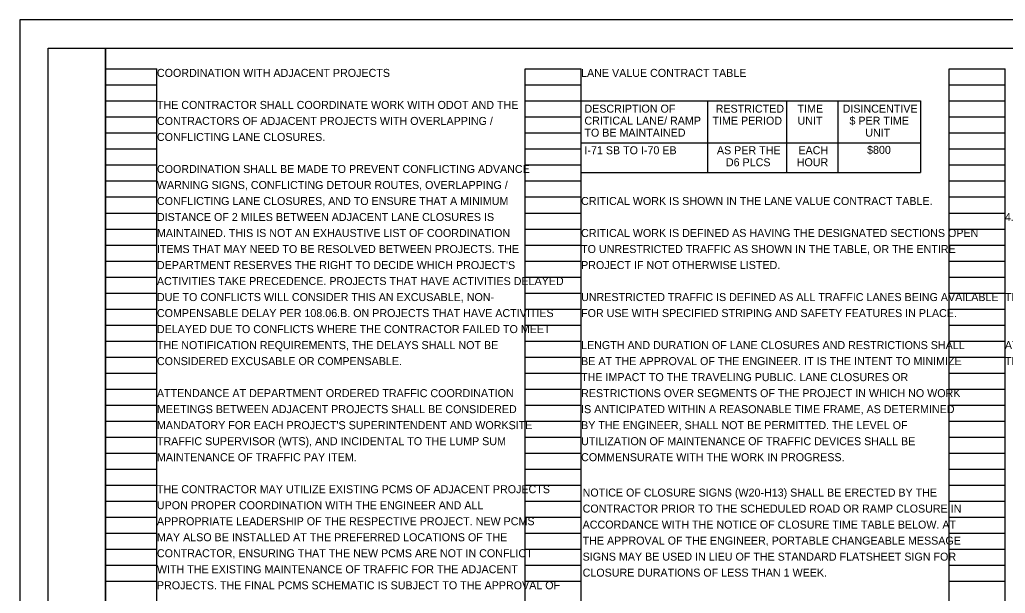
# Model space of a CAD drawing. Extents: x 0 to 34, y 0 to 22.
# Drawn here: x 0 to 17.24, y 11.97 to 22 of the extents above; entities that cross this region are included whole.
import ezdxf

# ---------------------------------------------------------------- set-up
doc = ezdxf.new("R2010")
doc.units = 0
for name, color, linetype in [('SH_Border', 7, 'Continuous'), ('SH_Cut_Line', 7, 'Continuous'), ('SH_Data', 7, 'Continuous'), ('SH_Text', 7, 'Continuous')]:
    doc.layers.add(name, color=color, linetype=linetype)

msp = doc.modelspace()

# ---------------------------------------------------------------- linework, layer by layer
at = {"layer": 'SH_Border'}
for points in [[(0.5, 21.5), (1.5, 21.5), (1.5, 0.5), (0.5, 0.5)], [(1.5, 21.5), (33.5, 21.5), (33.5, 0.5), (1.5, 0.5)]]:
    msp.add_lwpolyline(points, close=True, dxfattribs=at)
at = {"layer": 'SH_Cut_Line'}
msp.add_lwpolyline([(0, 0), (34, 0), (34, 22), (0, 22)], close=True, dxfattribs=at)
at = {"layer": 'SH_Data'}
for p, q in [((1.5, 0.98), (1.5, 21.14)), ((1.5, 21.14), (2.4, 21.14)), ((2.4, 0.98), (2.4, 21.14)), ((8.84, 0.98), (8.84, 21.14)), ((8.84, 21.14), (9.82, 21.14)), ((9.82, 0.98), (9.82, 21.14)), ((16.26, 0.98), (16.26, 21.14)), ((16.26, 21.14), (17.24, 21.14)), ((17.24, 0.98), (17.24, 21.14)), ((1.5, 20.86), (2.4, 20.86)), ((8.84, 20.86), (9.82, 20.86)), ((16.26, 20.86), (17.24, 20.86)), ((1.5, 20.58), (2.4, 20.58)), ((8.84, 20.58), (9.82, 20.58)), ((16.26, 20.58), (17.24, 20.58)), ((1.5, 20.3), (2.4, 20.3)), ((8.84, 20.3), (9.82, 20.3)), ((16.26, 20.3), (17.24, 20.3)), ((1.5, 20.02), (2.4, 20.02)), ((8.84, 20.02), (9.82, 20.02)), ((16.26, 20.02), (17.24, 20.02)), ((1.5, 19.74), (2.4, 19.74)), ((8.84, 19.74), (9.82, 19.74)), ((16.26, 19.74), (17.24, 19.74)), ((1.5, 19.46), (2.4, 19.46)), ((8.84, 19.46), (9.82, 19.46)), ((16.26, 19.46), (17.24, 19.46)), ((1.5, 19.18), (2.4, 19.18)), ((8.84, 19.18), (9.82, 19.18)), ((16.26, 19.18), (17.24, 19.18)), ((1.5, 18.9), (2.4, 18.9)), ((8.84, 18.9), (9.82, 18.9)), ((16.26, 18.9), (17.24, 18.9)), ((1.5, 18.62), (2.4, 18.62)), ((8.84, 18.62), (9.82, 18.62)), ((16.26, 18.62), (17.24, 18.62)), ((1.5, 18.34), (2.4, 18.34)), ((8.84, 18.34), (9.82, 18.34)), ((16.26, 18.34), (17.24, 18.34)), ((1.5, 18.06), (2.4, 18.06)), ((8.84, 18.06), (9.82, 18.06)), ((16.26, 18.06), (17.24, 18.06)), ((1.5, 17.78), (2.4, 17.78)), ((8.84, 17.78), (9.82, 17.78)), ((16.26, 17.78), (17.24, 17.78)), ((1.5, 17.5), (2.4, 17.5)), ((8.84, 17.5), (9.82, 17.5)), ((16.26, 17.5), (17.24, 17.5)), ((1.5, 17.22), (2.4, 17.22)), ((8.84, 17.22), (9.82, 17.22)), ((16.26, 17.22), (17.24, 17.22)), ((1.5, 16.94), (2.4, 16.94)), ((8.84, 16.94), (9.82, 16.94)), ((16.26, 16.94), (17.24, 16.94)), ((1.5, 16.66), (2.4, 16.66)), ((8.84, 16.66), (9.82, 16.66)), ((16.26, 16.66), (17.24, 16.66)), ((1.5, 16.38), (2.4, 16.38)), ((8.84, 16.38), (9.82, 16.38)), ((16.26, 16.38), (17.24, 16.38)), ((1.5, 16.1), (2.4, 16.1)), ((8.84, 16.1), (9.82, 16.1)), ((16.26, 16.1), (17.24, 16.1)), ((1.5, 15.82), (2.4, 15.82)), ((8.84, 15.82), (9.82, 15.82)), ((16.26, 15.82), (17.24, 15.82)), ((1.5, 15.54), (2.4, 15.54)), ((8.84, 15.54), (9.82, 15.54)), ((16.26, 15.54), (17.24, 15.54)), ((1.5, 15.26), (2.4, 15.26)), ((8.84, 15.26), (9.82, 15.26)), ((16.26, 15.26), (17.24, 15.26)), ((1.5, 14.98), (2.4, 14.98)), ((8.84, 14.98), (9.82, 14.98)), ((16.26, 14.98), (17.24, 14.98)), ((1.5, 14.7), (2.4, 14.7)), ((8.84, 14.7), (9.82, 14.7)), ((16.26, 14.7), (17.24, 14.7)), ((1.5, 14.42), (2.4, 14.42)), ((8.84, 14.42), (9.82, 14.42)), ((16.26, 14.42), (17.24, 14.42)), ((1.5, 14.14), (2.4, 14.14)), ((8.84, 14.14), (9.82, 14.14)), ((16.26, 14.14), (17.24, 14.14)), ((1.5, 13.86), (2.4, 13.86)), ((8.84, 13.86), (9.82, 13.86)), ((16.26, 13.86), (17.24, 13.86)), ((1.5, 13.58), (2.4, 13.58)), ((8.84, 13.58), (9.82, 13.58)), ((16.26, 13.58), (17.24, 13.58)), ((1.5, 13.3), (2.4, 13.3)), ((8.84, 13.3), (9.82, 13.3)), ((16.26, 13.3), (17.24, 13.3)), ((1.5, 13.02), (2.4, 13.02)), ((8.84, 13.02), (9.82, 13.02)), ((16.26, 13.02), (17.24, 13.02)), ((1.5, 12.74), (2.4, 12.74)), ((8.84, 12.74), (9.82, 12.74)), ((16.26, 12.74), (17.24, 12.74)), ((1.5, 12.46), (2.4, 12.46)), ((8.84, 12.46), (9.82, 12.46)), ((16.26, 12.46), (17.24, 12.46)), ((1.5, 12.18), (2.4, 12.18)), ((8.84, 12.18), (9.82, 12.18)), ((16.26, 12.18), (17.24, 12.18))]:
    msp.add_line(p, q, dxfattribs=at)
at = {"layer": 'SH_Text'}
for p, q in [((9.82, 20.58), (15.756, 20.58)), ((9.82, 19.331), (9.82, 20.58)), ((12.032, 20.58), (12.032, 19.331)), ((13.415, 20.58), (13.415, 19.331)), ((14.309, 20.58), (14.309, 19.331)), ((15.756, 20.58), (15.756, 19.331)), ((9.818, 19.847), (15.756, 19.847)), ((9.819, 19.331), (15.756, 19.331))]:
    msp.add_line(p, q, dxfattribs=at)

# ---------------------------------------------------------------- texts
for s, p in [('COORDINATION WITH ADJACENT PROJECTS', (2.4, 21)), ('LANE VALUE CONTRACT TABLE', (9.82, 21)), ('THE CONTRACTOR SHALL COORDINATE WORK WITH ODOT AND THE ', (2.4, 20.44)), ('DESCRIPTION OF', (9.878, 20.375)), ('RESTRICTED ', (12.174, 20.375)), ('DISINCENTIVE ', (14.395, 20.375)), ('TIME ', (13.606, 20.375)), ('CONTRACTORS OF ADJACENT PROJECTS WITH OVERLAPPING / ', (2.4, 20.16)), ('CRITICAL LANE/ RAMP', (9.878, 20.165)), ('TIME PERIOD', (12.118, 20.165)), ('UNIT', (13.606, 20.165)), ('$ PER TIME', (14.514, 20.165)), ('CONFLICTING LANE CLOSURES.', (2.4, 19.88)), ('TO BE MAINTAINED', (9.878, 19.955)), ('UNIT', (14.791, 19.955)), ('I-71 SB TO I-70 EB', (9.878, 19.647)), ('AS PER THE', (12.196, 19.647)), ('EACH ', (13.621, 19.648)), ('$800', (14.822, 19.654)), ('D6 PLCS', (12.353, 19.437)), ('HOUR', (13.592, 19.438)), ('COORDINATION SHALL BE MADE TO PREVENT CONFLICTING ADVANCE ', (2.4, 19.32)), ('WARNING SIGNS, CONFLICTING DETOUR ROUTES, OVERLAPPING / ', (2.4, 19.04)), ('CONFLICTING LANE CLOSURES, AND TO ENSURE THAT A MINIMUM ', (2.4, 18.76)), ('CRITICAL WORK IS SHOWN IN THE LANE VALUE CONTRACT TABLE.', (9.82, 18.76)), ('DISTANCE OF 2 MILES BETWEEN ADJACENT LANE CLOSURES IS ', (2.4, 18.48)), ('4. NO LANE OR SHOULDER CLOSURES SHALL BE IN PLACE WHEN NO WORK', (17.233, 18.48)), ('MAINTAINED. THIS IS NOT AN EXHAUSTIVE LIST OF COORDINATION ', (2.4, 18.2)), ('CRITICAL WORK IS DEFINED AS HAVING THE DESIGNATED SECTIONS OPEN ', (9.82, 18.2)), ('ITEMS THAT MAY NEED TO BE RESOLVED BETWEEN PROJECTS. THE ', (2.4, 17.92)), ('TO UNRESTRICTED TRAFFIC AS SHOWN IN THE TABLE, OR THE ENTIRE ', (9.82, 17.92)), ("DEPARTMENT RESERVES THE RIGHT TO DECIDE WHICH PROJECT'S ", (2.4, 17.64)), ('PROJECT IF NOT OTHERWISE LISTED.', (9.82, 17.64)), ('ACTIVITIES TAKE PRECEDENCE. PROJECTS THAT HAVE ACTIVITIES DELAYED ', (2.4, 17.36)), ('DUE TO CONFLICTS WILL CONSIDER THIS AN EXCUSABLE, NON-', (2.4, 17.08)), ('UNRESTRICTED TRAFFIC IS DEFINED AS ALL TRAFFIC LANES BEING AVAILABLE ', (9.82, 17.08)), ('THE LATEST REVISION OF THE OMUTCD.', (17.233, 17.08)), ('COMPENSABLE DELAY PER 108.06.B. ON PROJECTS THAT HAVE ACTIVITIES ', (2.4, 16.8)), ('FOR USE WITH SPECIFIED STRIPING AND SAFETY FEATURES IN PLACE.', (9.82, 16.8)), ('DELAYED DUE TO CONFLICTS WHERE THE CONTRACTOR FAILED TO MEET ', (2.4, 16.52)), ('THE NOTIFICATION REQUIREMENTS, THE DELAYS SHALL NOT BE ', (2.4, 16.24)), ('LENGTH AND DURATION OF LANE CLOSURES AND RESTRICTIONS SHALL ', (9.82, 16.24)), ('AT LEAST ONE SIDE AT ALL TIMES AT LOCATIONS WHERE PEDESTRIAN ', (17.233, 16.24)), ('CONSIDERED EXCUSABLE OR COMPENSABLE.', (2.4, 15.96)), ('BE AT THE APPROVAL OF THE ENGINEER. IT IS THE INTENT TO MINIMIZE ', (9.82, 15.96)), ('TRAFFIC IS CURRENTLY MAINTAINED.', (17.233, 15.96)), ('THE IMPACT TO THE TRAVELING PUBLIC. LANE CLOSURES OR ', (9.82, 15.68)), ('ATTENDANCE AT DEPARTMENT ORDERED TRAFFIC COORDINATION ', (2.4, 15.4)), ('RESTRICTIONS OVER SEGMENTS OF THE PROJECT IN WHICH NO WORK ', (9.82, 15.4)), ('MEETINGS BETWEEN ADJACENT PROJECTS SHALL BE CONSIDERED ', (2.4, 15.12)), ('IS ANTICIPATED WITHIN A REASONABLE TIME FRAME, AS DETERMINED ', (9.82, 15.12)), ("MANDATORY FOR EACH PROJECT'S SUPERINTENDENT AND WORKSITE ", (2.4, 14.84)), ('BY THE ENGINEER, SHALL NOT BE PERMITTED. THE LEVEL OF ', (9.82, 14.84)), ('TRAFFIC SUPERVISOR (WTS), AND INCIDENTAL TO THE LUMP SUM ', (2.4, 14.56)), ('UTILIZATION OF MAINTENANCE OF TRAFFIC DEVICES SHALL BE ', (9.82, 14.56)), ('MAINTENANCE OF TRAFFIC PAY ITEM.', (2.4, 14.28)), ('COMMENSURATE WITH THE WORK IN PROGRESS.', (9.82, 14.28)), ('THE CONTRACTOR MAY UTILIZE EXISTING PCMS OF ADJACENT PROJECTS ', (2.4, 13.72)), ('NOTICE OF CLOSURE SIGNS (W20-H13) SHALL BE ERECTED BY THE ', (9.847, 13.661)), ('UPON PROPER COORDINATION WITH THE ENGINEER AND ALL ', (2.4, 13.44)), ('CONTRACTOR PRIOR TO THE SCHEDULED ROAD OR RAMP CLOSURE IN ', (9.847, 13.381)), ('APPROPRIATE LEADERSHIP OF THE RESPECTIVE PROJECT. NEW PCMS ', (2.4, 13.16)), ('ACCORDANCE WITH THE NOTICE OF CLOSURE TIME TABLE BELOW. AT ', (9.847, 13.101)), ('MAY ALSO BE INSTALLED AT THE PREFERRED LOCATIONS OF THE ', (2.4, 12.88)), ('THE APPROVAL OF THE ENGINEER, PORTABLE CHANGEABLE MESSAGE ', (9.847, 12.821)), ('CONTRACTOR, ENSURING THAT THE NEW PCMS ARE NOT IN CONFLICT ', (2.4, 12.6)), ('SIGNS MAY BE USED IN LIEU OF THE STANDARD FLATSHEET SIGN FOR ', (9.847, 12.541)), ('WITH THE EXISTING MAINTENANCE OF TRAFFIC FOR THE ADJACENT ', (2.4, 12.32)), ('CLOSURE DURATIONS OF LESS THAN 1 WEEK.', (9.847, 12.261)), ('PROJECTS. THE FINAL PCMS SCHEMATIC IS SUBJECT TO THE APPROVAL OF ', (2.4, 12.04))]:
    msp.add_text(s, height=0.14, dxfattribs=at).set_placement(p)

doc.saveas('drawing.dxf')
